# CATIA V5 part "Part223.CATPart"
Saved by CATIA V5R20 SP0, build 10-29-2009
Part number: DFA 168700-1
Revision: ANY
Definition: UNKNOWN
Nomenclature: DFA 168700-1
Source: Unknown
Bounding box of the stored display mesh (mm): x -3.804 to 3.804, y 0.28 to 2.5, z -4 to 4
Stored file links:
  C:\Users\Utente\Desktop\IO LAVORO\3D X SITO CF\CUMSA\3D files FA\FA 200710-21\Part223.CATPart

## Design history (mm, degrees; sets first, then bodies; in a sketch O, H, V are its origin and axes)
Body1 "Cortar-Extruir1" (main body)
  Solid1: solid without history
